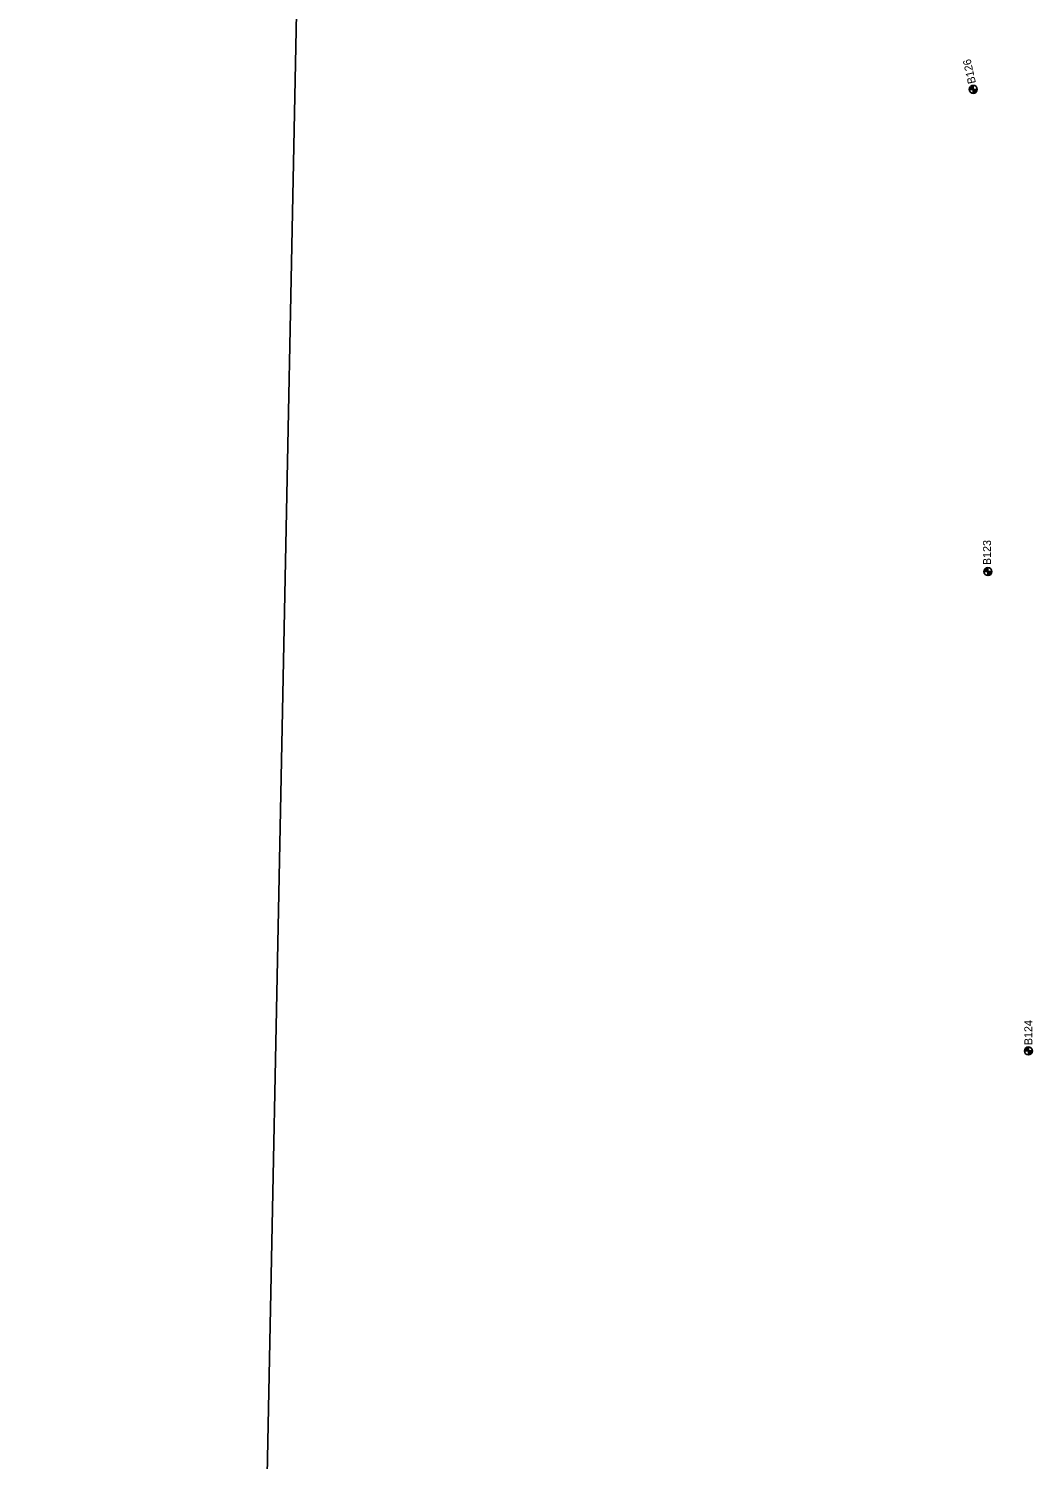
# Model space of a CAD drawing. Extents: x 345549 to 379569, y 127949 to 230467.
# Drawn here: x 355372 to 356628, y 196011 to 197800 of the extents above; entities that cross this region are included whole.
import ezdxf

# ---------------------------------------------------------------- set-up
doc = ezdxf.new("R2010")
doc.units = 0
for name, color, linetype in [('E_RDWY', 7, 'Continuous'), ('E_SOIL_BORE1 [KAPUR_CADDS_LEVELS]', 7, 'Continuous'), ('E_SOIL_BORE2 [KAPUR_CADDS_LEVELS]', 7, 'Continuous'), ('P_MARK', 7, 'Continuous')]:
    doc.layers.add(name, color=color, linetype=linetype)

msp = doc.modelspace()

# ---------------------------------------------------------------- linework, layer by layer
at = {"layer": 'E_RDWY'}
msp.add_line((355372.5, 181177.5), (356094.5, 217027.6), dxfattribs=at)
at = {"layer": 'P_MARK'}
for p, q in [((356553.9, 197728.7), (356553.9, 197718.7)), ((356548.9, 197723.7), (356558.9, 197723.7)), ((356567.3, 197121), (356577.3, 197121)), ((356572.3, 197126), (356572.3, 197116)), ((356617.9, 196521.9), (356627.9, 196521.9)), ((356622.9, 196526.9), (356622.9, 196516.9))]:
    msp.add_line(p, q, dxfattribs=at)
for centre in [(356553.9, 197723.7), (356572.3, 197121), (356622.9, 196521.9)]:
    msp.add_circle(centre, 5, dxfattribs=at)
for centre, radius, start, end in [((356553.9, 197723.7), 4.5, 89.9869, 179.9869), ((356553.9, 197723.7), 4, 89.9869, 179.9869), ((356553.9, 197723.7), 3.5, 89.9869, 179.9869), ((356553.9, 197723.7), 3, 89.9869, 179.9869), ((356553.9, 197723.7), 2.5, 89.9869, 179.9869), ((356553.9, 197723.7), 2, 89.9869, 179.9869), ((356553.9, 197723.7), 1.5, 89.9869, 179.9869), ((356553.9, 197723.7), 1, 89.9869, 179.9869), ((356553.9, 197723.7), 0.5, 89.9869, 179.9869), ((356553.9, 197723.7), 4.5, 269.9869, 359.9869), ((356553.9, 197723.7), 4, 269.9869, 359.9869), ((356553.9, 197723.7), 3.5, 269.9869, 359.9869), ((356553.9, 197723.7), 3, 269.9869, 359.9869), ((356553.9, 197723.7), 2.5, 269.9869, 359.9869), ((356553.9, 197723.7), 2, 269.9869, 359.9869), ((356553.9, 197723.7), 1.5, 269.9869, 359.9869), ((356553.9, 197723.7), 1, 269.9869, 359.9869), ((356553.9, 197723.7), 0.5, 269.9869, 359.9869), ((356572.3, 197121), 4.5, 89.9869, 179.9869), ((356572.3, 197121), 4, 89.9869, 179.9869), ((356572.3, 197121), 3.5, 89.9869, 179.9869), ((356572.3, 197121), 3, 89.9869, 179.9869), ((356572.3, 197121), 2.5, 89.9869, 179.9869), ((356572.3, 197121), 2, 89.9869, 179.9869), ((356572.3, 197121), 1.5, 89.9869, 179.9869), ((356572.3, 197121), 1, 89.9869, 179.9869), ((356572.3, 197121), 0.5, 89.9869, 179.9869), ((356572.3, 197121), 4.5, 269.9869, 359.9869), ((356572.3, 197121), 4, 269.9869, 359.9869), ((356572.3, 197121), 3.5, 269.9869, 359.9869), ((356572.3, 197121), 3, 269.9869, 359.9869), ((356572.3, 197121), 2.5, 269.9869, 359.9869), ((356572.3, 197121), 2, 269.9869, 359.9869), ((356572.3, 197121), 1.5, 269.9869, 359.9869), ((356572.3, 197121), 1, 269.9869, 359.9869), ((356572.3, 197121), 0.5, 269.9869, 359.9869), ((356622.9, 196521.9), 4.5, 89.9869, 179.9869), ((356622.9, 196521.9), 4, 89.9869, 179.9869), ((356622.9, 196521.9), 3.5, 89.9869, 179.9869), ((356622.9, 196521.9), 3, 89.9869, 179.9869), ((356622.9, 196521.9), 2.5, 89.9869, 179.9869), ((356622.9, 196521.9), 2, 89.9869, 179.9869), ((356622.9, 196521.9), 1.5, 89.9869, 179.9869), ((356622.9, 196521.9), 1, 89.9869, 179.9869), ((356622.9, 196521.9), 0.5, 89.9869, 179.9869), ((356622.9, 196521.9), 4.5, 269.9869, 359.9869), ((356622.9, 196521.9), 4, 269.9869, 359.9869), ((356622.9, 196521.9), 3.5, 269.9869, 359.9869), ((356622.9, 196521.9), 3, 269.9869, 359.9869), ((356622.9, 196521.9), 2.5, 269.9869, 359.9869), ((356622.9, 196521.9), 2, 269.9869, 359.9869), ((356622.9, 196521.9), 1.5, 269.9869, 359.9869), ((356622.9, 196521.9), 1, 269.9869, 359.9869), ((356622.9, 196521.9), 0.5, 269.9869, 359.9869)]:
    msp.add_arc(centre, radius, start, end, dxfattribs=at)

# ---------------------------------------------------------------- texts
at = {"layer": 'E_SOIL_BORE1 [KAPUR_CADDS_LEVELS]'}
msp.add_text('B124', height=10, rotation=89.9869, dxfattribs=at).set_placement((356627.8, 196529.2))
at = {"layer": 'E_SOIL_BORE2 [KAPUR_CADDS_LEVELS]'}
for s, rotation, p in [('B126', 102.6348, (356557.3, 197731.8)), ('B123', 89.9869, (356576.1, 197129.2))]:
    msp.add_text(s, height=10, rotation=rotation, dxfattribs=at).set_placement(p)

doc.saveas('drawing.dxf')
